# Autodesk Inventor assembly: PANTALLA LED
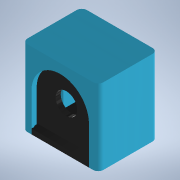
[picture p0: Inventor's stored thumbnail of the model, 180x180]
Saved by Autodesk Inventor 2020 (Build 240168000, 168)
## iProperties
Created: 2022-09
Part Number: PANTALLA LED
Document SubType Name: Assembly
Designer: SEBAS
Author: SEBAS
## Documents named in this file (5)
- D:\TRABAJO UNIVERSIDAD\MOLDE LATERAL EXTENDIDO\PANTALLA LED\PANTALLA LED.iam
- D:\TRABAJO UNIVERSIDAD\MOLDE LATERAL EXTENDIDO\MOLDE LATERAL\MOLDE LATERAL.ipt
- D:\TRABAJO UNIVERSIDAD\MOLDE LATERAL EXTENDIDO\TAPA\TAPA.ipt
- D:\TRABAJO UNIVERSIDAD\MOLDE LATERAL EXTENDIDO\LENTE\LENTE.ipt
- D:\TRABAJO UNIVERSIDAD\MOLDE LATERAL EXTENDIDO\TAPA SUPERIOR\TAPA SUPERIOR.ipt
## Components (4 placed, 4 different names)
1. MOLDE LATERAL:1 — Nivelación:1, Nivelación:2, Nivelación:3, Coincidencia:2, Coincidencia:3, Coincidencia:4, Coincidencia:5, Nivelación:4, Coincidencia:6, Nivelación:5, Coincidencia:7
2. LENTE:1 — Coincidencia:2, Coincidencia:3, Coincidencia:4
3. TAPA SUPERIOR:1 — Coincidencia:5, Nivelación:4, Coincidencia:6
4. TAPA:1 — Nivelación:5, Coincidencia:7
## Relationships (11: Mate 6, Flush 5)
- Nivelación:1 [Flush]: MOLDE LATERAL:1
- Nivelación:2 [Flush]: MOLDE LATERAL:1
- Nivelación:3 [Flush]: MOLDE LATERAL:1
- Coincidencia:2 [Mate]: MOLDE LATERAL:1 ↔ LENTE:1
- Coincidencia:3 [Mate]: MOLDE LATERAL:1 ↔ LENTE:1
- Coincidencia:4 [Mate]: MOLDE LATERAL:1 ↔ LENTE:1
- Coincidencia:5 [Mate]: MOLDE LATERAL:1 ↔ TAPA SUPERIOR:1
- Nivelación:4 [Flush]: MOLDE LATERAL:1 ↔ TAPA SUPERIOR:1
- Coincidencia:6 [Mate]: MOLDE LATERAL:1 ↔ TAPA SUPERIOR:1
- Nivelación:5 [Flush]: MOLDE LATERAL:1 ↔ TAPA:1
- Coincidencia:7 [Mate]: MOLDE LATERAL:1 ↔ TAPA:1
